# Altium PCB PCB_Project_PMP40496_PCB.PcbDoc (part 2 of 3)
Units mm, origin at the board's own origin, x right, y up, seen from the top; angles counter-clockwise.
Board outline 140 x 100 mm, 4 copper layers (Top Layer, Signal Layer 1, Signal Layer 2, Bottom Layer), stack 1.565 mm thick; 186 components, 128 nets, 605 pads, 270 vias.
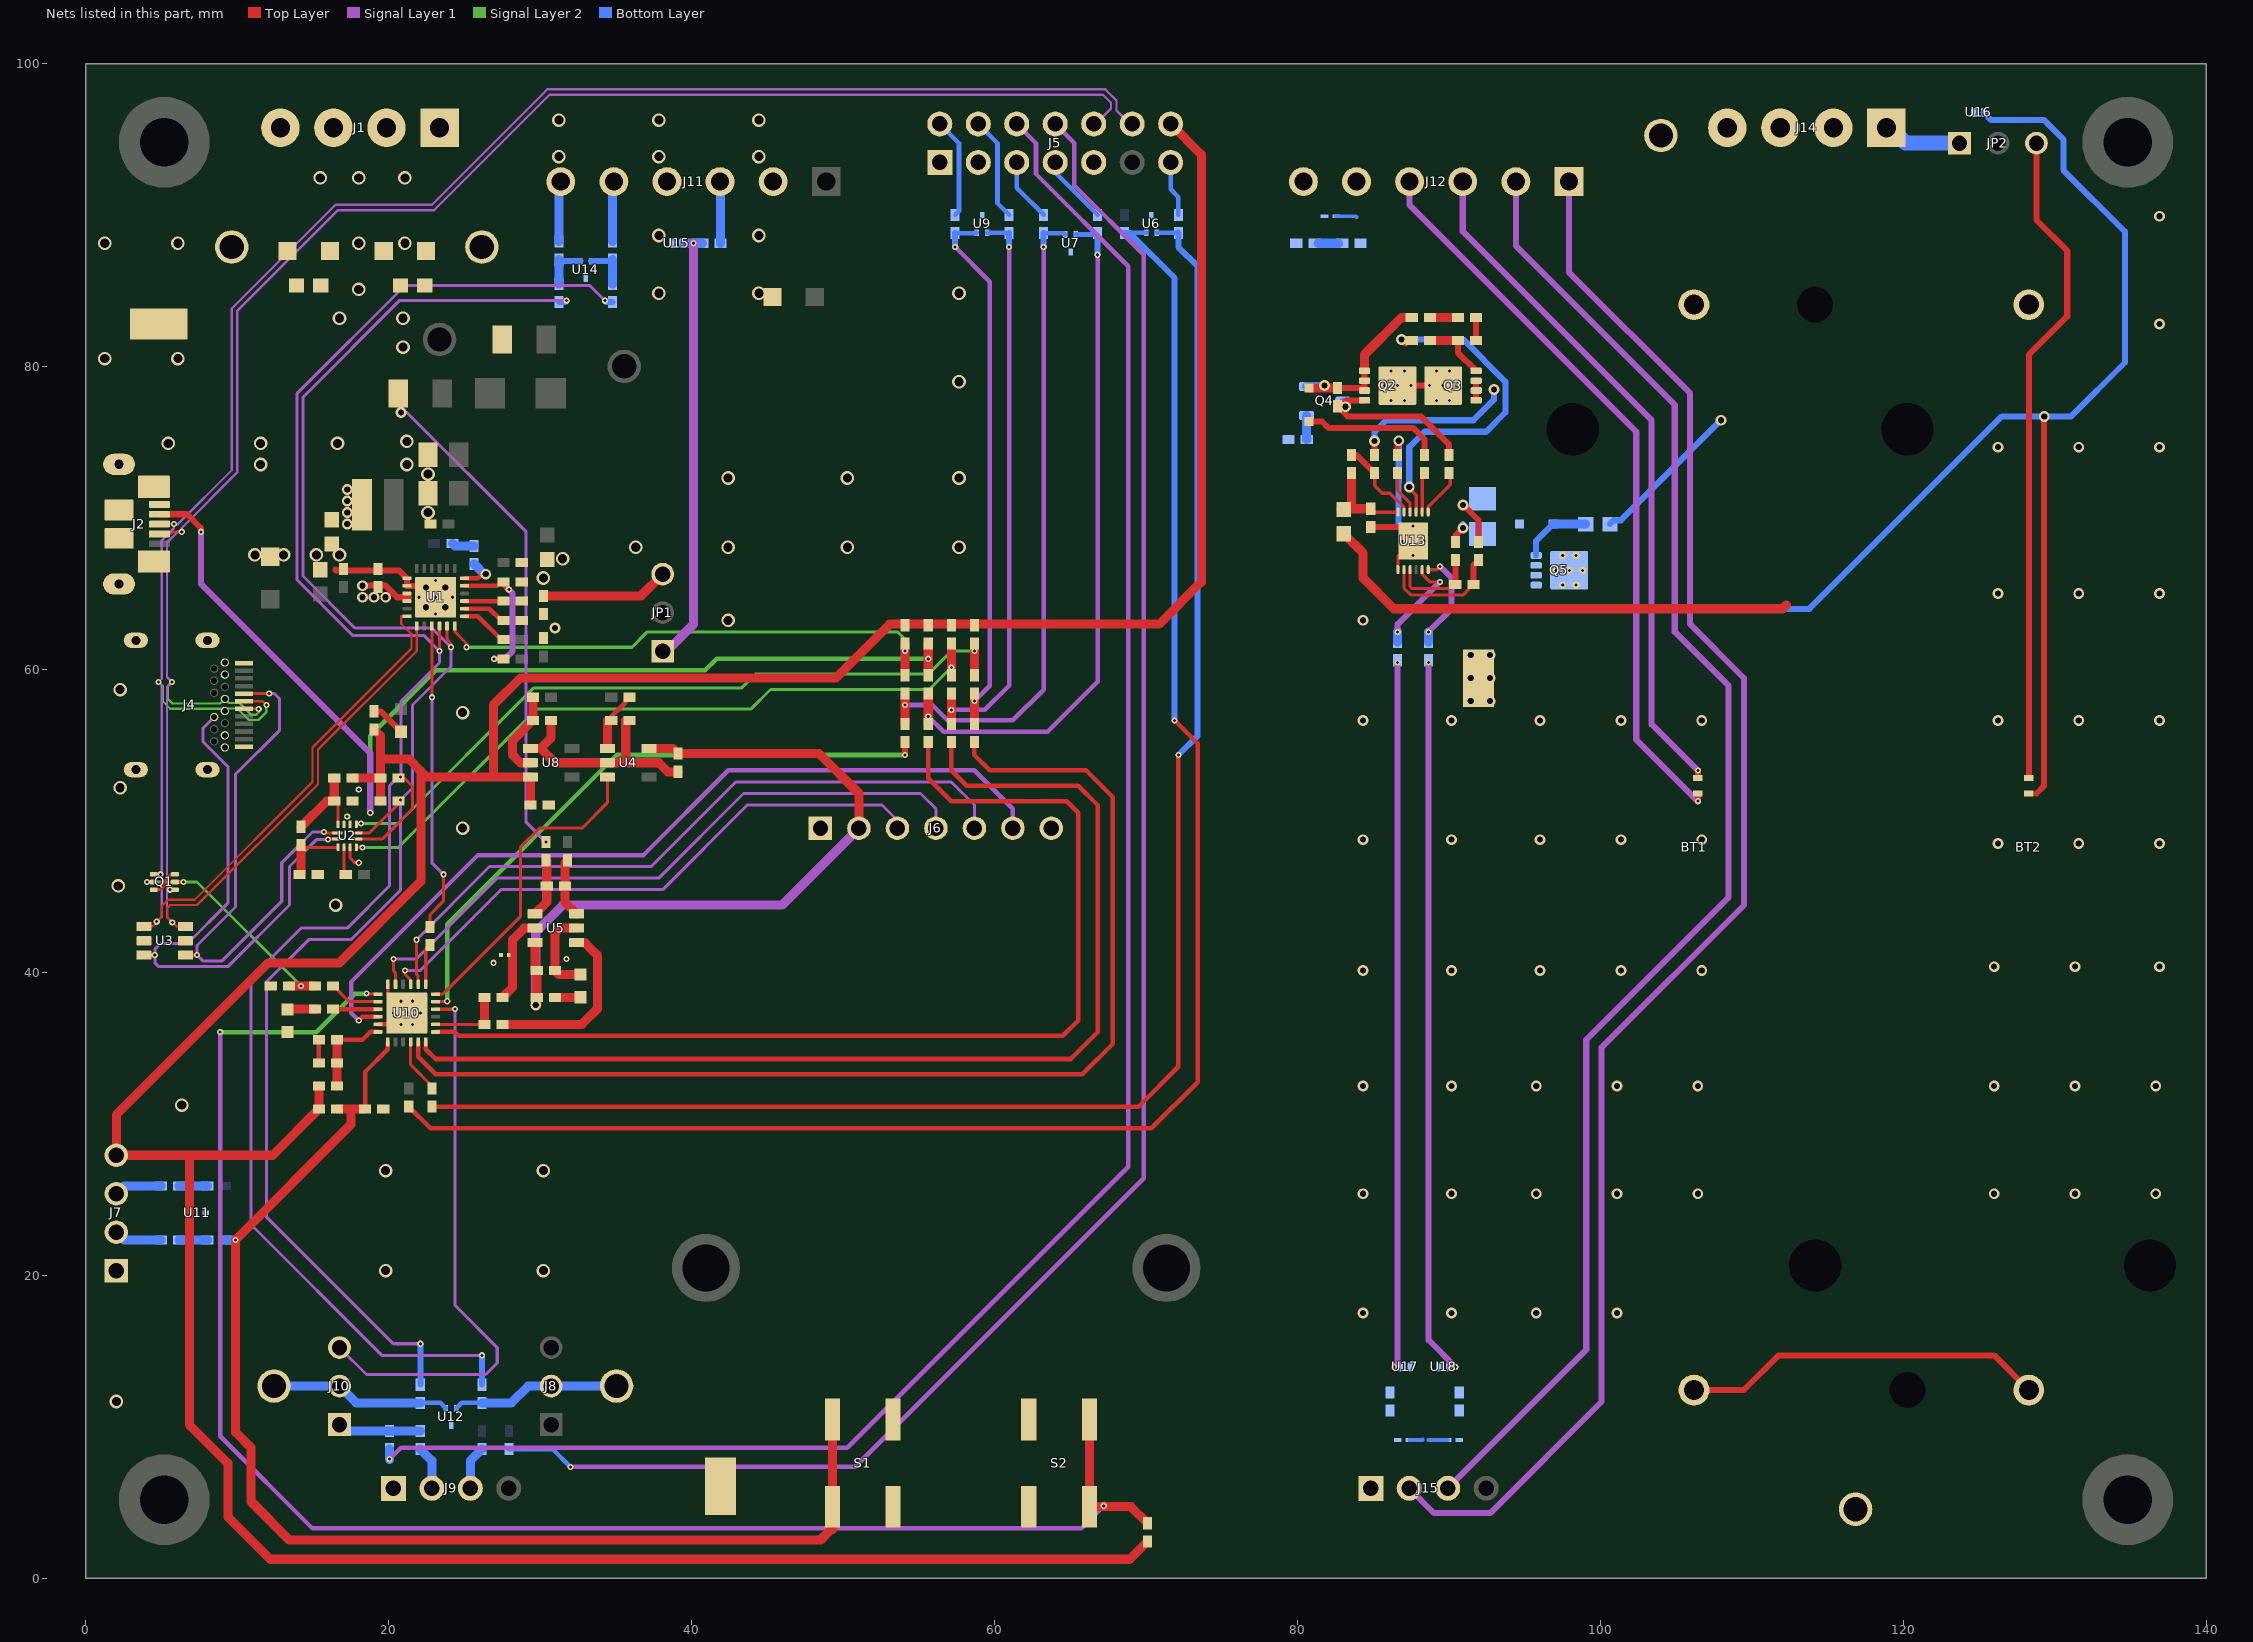
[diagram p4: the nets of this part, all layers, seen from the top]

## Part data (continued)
R5 R11 R12 R38 R41 R44 R49 R51 R53 R54 R68: library part CMP-0026994-4, "RES, 10 k, 5%, 0.1 W, AEC-Q200 Grade 0, 0402", Manufacturer=Panasonic, Power_W=100mW, Supplier Part Number 1=P10KJCT-ND, TempCo="200 ppm/C", Tolerance_%=5%, Value2=0.1W, Value_Code=10k0, ValueDisplayed=10k
R6: library part CMP-0026464-2, "RES, 5.23 k, 1%, 0.063 W, AEC-Q200 Grade 0, 0402", Manufacturer=Vishay-Dale, Power_W=63mW, Supplier Part Number 1=541-5.23KLCT-ND, TempCo="100 ppm/C", Tolerance_%=1%, Value2=0.063W, Value_Code=5k23, ValueDisplayed=5.23k
R7 R13 R14 R16 R17 R18 R19 R20 R21 R22 R23 R27 R28 R29 R30 R32 R33 R34 R35 R37 R39 R40 R42 R43 R61 R62 R64 R65 R66 R69 R70 R72 R73 R74 R75 R76 R77 R78 R79 R80: library part CMP-0026722-1, "RES, 100, 1%, 0.063 W, 0402", Manufacturer="Yageo America", Power_W=63mW, Supplier Part Number 1=311-100LRCT-ND, TempCo="100 ppm/C", Tolerance_%=1%, Value2=0.063W, Value_Code=100R, ValueDisplayed=100
R8: library part CMP-0026730-1, "RES, 30.1 k, 1%, 0.063 W, 0402", Manufacturer="Yageo America", Power_W=63mW, Supplier Part Number 1=311-30.1KLRCT-ND, TempCo="100 ppm/C", Tolerance_%=1%, Value2=0.063W, Value_Code=30k1, ValueDisplayed=30.1k
R9 R15 R26 R31: "RES, 1.00, 1%, 0.063 W, 0402", Manufacturer=Vishay-Dale, Power_W=0.063, Supplier Part Number 1=541-1.00LLCT-ND, TempCo="100 ppm/C", Tolerance_%=1, Value1=1%, Value2=0.063W, Value_Code=1R00, ValueDisplayed=1.00
R10: library part CMP-0026603-2, "RES, 909 k, 1%, 0.063 W, AEC-Q200 Grade 0, 0402", Manufacturer=Vishay-Dale, Power_W=63mW, Supplier Part Number 1=541-909KLCT-ND, TempCo="100 ppm/C", Tolerance_%=1%, Value2=0.063W, Value_Code=909k
R24 R25 R63: library part CMP-0026717-1, "RES, 10.0, 1%, 0.063 W, 0402", Manufacturer=Rohm, Power_W=63mW, Supplier Part Number 1=RHM10.0LCT-ND, TempCo="100 ppm/C", Tolerance_%=1%, Value2=0.063W, Value_Code=10R0, ValueDisplayed=10.0
R36 R45: library part CMP-0026737-1, "RES, 47.0 k, 1%, 0.0625 W, 0402", Manufacturer="Yageo America", Power_W=62.5mW, Supplier Part Number 1=311-47.0KLRCT-ND, TempCo="100 ppm/C", Tolerance_%=1%, Value2=0.0625W, Value_Code=47k0, ValueDisplayed=47.0k
R46 R47 R48: library part CMP-0026668-1, "RES, 1.50 k, 1%, 0.1 W, AEC-Q200 Grade 0, 0402", Manufacturer=Panasonic, Power_W=100mW, Supplier Part Number 1=P1.50KLCT-ND, TempCo="100 ppm/C", Tolerance_%=1%, Value2=0.1W, Value_Code=1k50, ValueDisplayed=1.50k
R50: library part CMP-0026852-3, "RES, 1.0 k, 5%, 0.063 W, AEC-Q200 Grade 0, 0402", Manufacturer=Vishay-Dale, Power_W=63mW, Supplier Part Number 1=541-1.0KJCT-ND, TempCo="200 ppm/C", Tolerance_%=5%, Value2=0.063W, Value_Code=1k00, ValueDisplayed=1.0k
R52: library part CMP-0026823-3, "RES, 100 k, 5%, 0.063 W, AEC-Q200 Grade 0, 0402", Manufacturer=Vishay-Dale, Power_W=63mW, Supplier Part Number 1=541-100KJCT-ND, TempCo="200 ppm/C", Tolerance_%=5%, Value2=0.063W, Value_Code=100k
R55 R56: library part CMP-0026826-2, "RES, 10 M, 5%, 0.063 W, AEC-Q200 Grade 0, 0402", Manufacturer=Vishay-Dale, Power_W=63mW, Supplier Part Number 1=541-10MJCT-ND, TempCo="200 ppm/C", Tolerance_%=5%, Value2=0.063W, Value_Code=10M0, ValueDisplayed=10M
R57: library part CMP-0025899-5, "RES, 1.0 k, 5%, 0.1 W, 0603", Manufacturer=Yageo, Power_W=100mW, Supplier Part Number 1=311-1.0KGRCT-ND, TempCo="100 ppm/C", Tolerance_%=5%, Value2=0.1W, Value_Code=1k00, ValueDisplayed=1.0k
R58: library part CMP-0026434-2, "RES, 4.99, 1%, 0.063 W, AEC-Q200 Grade 0, 0402", Manufacturer=Vishay-Dale, Power_W=63mW, Supplier Part Number 1=541-4.99LLCT-ND, TempCo="100 ppm/C", Tolerance_%=1%, Value2=0.063W, Value_Code=4R99, ValueDisplayed=4.99
R59 R60: library part CMP-0026951-5, "RES, 5.1 k, 5%, 0.063 W, AEC-Q200 Grade 0, 0402", Manufacturer=Vishay-Dale, Power_W=63mW, Supplier Part Number 1=541-5.1KJCT-ND, TempCo="200 ppm/C", Tolerance_%=5%, Value2=0.063W, Value_Code=5k10, ValueDisplayed=5.1k
R67: library part CMP-0021991-4, "RES, 100, 1%, 0.1 W, AEC-Q200 Grade 0, 0603", Manufacturer=Vishay-Dale, Power_W=100mW, Supplier Part Number 1=541-100HCT-ND, TempCo="100 ppm/C", Tolerance_%=1%, Value2=0.1W, Value_Code=100R, ValueDisplayed=100
R71: library part CMP-0018569-2, "RES, 0.001, 1%, 1 W, 1206", Manufacturer=Vishay-Dale, Power_W=1W, Supplier Part Number 1=54X6165, TempCo="275 ppm/C", Tolerance_%=1%, Value_Code=1L000, ValueDisplayed=0.001
RT1 RT2: library part CMP-0002344-2, "Thermistor NTC, 10.0k ohm, 1%, 0402", Manufacturer=MuRata, Power_W=100mW, Supplier Part Number 1=490-4801-1-ND, Tolerance_%=1%
S1 S2: library part CMP-0002310-1, "SWITCH TACTILE SPST-NO 0.05A 12V", CurrentRating_mA=50A, Manufacturer="Omron Electronic Components", Supplier Part Number 1=SW1064CT-ND
SH-JP1 SH-JP2 SH-JP3 SH-JP4: library part CMP-0003614-1, "Shunt, 100mil, Gold plated, Black", Alternate Manufacturer=Samtec, Alternate PartNumber=SNT-100-BK-G, Manufacturer=3M, Supplier Part Number 1=3M9580-ND
TP1 TP2 TP9: "Test Point, Multipurpose, Red, TH", Color=Red, Manufacturer=Keystone, Supplier Part Number 1=36-5010-ND
TP3 TP4 TP10: "Test Point, Multipurpose, Orange, TH", Color=Orange, Manufacturer=Keystone, Supplier Part Number 1=36-5013-ND
TP5 TP6 TP11: library part 5019, "Test Point, Miniature, SMT", Manufacturer=Keystone, Supplier Part Number 1=36-5019TR-ND
TP7: "Test Point, Compact, White, TH", Color=White, Manufacturer=Keystone, Supplier Part Number 1=36-5007-ND
TP8: "Test Point, Compact, Orange, TH", Color=Orange, Manufacturer=Keystone, Supplier Part Number 1=36-5008-ND
U1: library part CMP-0076878-5, "I2C Controlled, 2-Cell, 2A Boost-Mode Battery Charger for USB Input, RGE0024H (VQFN-24)", Alternate Manufacturer="Texas Instruments", Alternate PartNumber=BQ25881RGET
U2: library part CMP-0073635-2, "USB Type-C Configuration Channel Logic and Port Control, RWB0012A (X2QFN-12)", Alternate Manufacturer="Texas Instruments", Operating Temperature Range="-40 to 85 C", Rating=Catalog
U3: library part CMP-0066605-1, "Quad-Channel High-Speed ESD Protection Device, DBV0006A (SOT-23-6)", Alternate Manufacturer="Texas Instruments"
U4: library part CMP-0073793-1, "150-mA, 30-V, Ultra-Low IQ, Wide Input Low-Dropout Regulator with Reverse Current Protection, DBV0005A (SOT-23-5)", Alternate Manufacturer="Texas Instruments", Alternate PartNumber=TPS70933DBVT
U5: library part CMP-0013232-2, "Bidirectional, Low- and High-Side Measurement, Multichannel, Voltage Output, Current-Sense Amplifier, DBV0006A (SOT-6)", Alternate Manufacturer="Texas Instruments"
U6 U7 U9 U11 U12 U14: library part CMP-0043103-2, "ESD / Surge Solution for High Speed, Low Voltage Interface, 2 Channels, -40 to +85 degC, 3-pin SOT (DRT), Green (RoHS & no Sb/Br)", Breakdown Voltage(Min)(V)=4.5, Differential Capacitance(pF)=0.05, IO Capacitance(Typ)(pF)=0.7, IO Leakage Current(nA)=10, Manufacturer="Texas Instruments"
U8: library part CMP-0035588-1, "Single Output LDO, 150 mA, Fixed 3.3 V Output, 2.5 to 24 V Input, with Ultra-Low IQ, 5-pin SOT-23 (DBV), -40 to 125 degC, Green (RoHS & no Sb/Br)", Manufacturer="Texas Instruments"
U10: library part CMP-0076607-2, "MSP430FR2433 16 MHz Ultra-Low-Power Microcontroller with 16 KB FRAM, 4 KB RAM, 19 IO, 4 Timers, RGE0024H (VQFN-24)", Alternate Manufacturer="Texas Instruments", Alternate PartNumber=MSP430FR2433IRGET
U13: library part CMP-0076164-1, "Battery Fuel Gauge with Integrated Protector for 1-2 Series Packs, DRZ0012A (VSON-12)", Alternate Manufacturer="Texas Instruments", Alternate PartNumber=BQ28Z610DRZT
U15 U16 U17 U18: library part CMP-0084110-2, "1-Channel 30 kV ESD Protection Diode With Low Clamping Voltage in 0402 Package, DPY0002A (X1SON-2)", Alternate Manufacturer="Texas Instruments", Operating Temperature Range="-40 to 125 C", Rating=Catalog

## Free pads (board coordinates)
  round 6 hole 3.2: 1(5.2,5.2) 1(5.2,94.8) 1(134.8,5.2) 1(134.8,94.8)
  round 4.5 hole 3.1: 1(40.948,20.502) 1(71.348,20.502)

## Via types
v1: diameter 0.406, hole 0.203, Top Layer to Bottom Layer, 92 vias
v2: diameter 0.711, hole 0.406, Top Layer to Bottom Layer, 89 vias
v3: diameter 0.9, hole 0.6, Top Layer to Bottom Layer, tented top, 59 vias
v4: diameter 0.5, hole 0.2, Top Layer to Bottom Layer, 27 vias
v5: diameter 0.5, hole 0.2, Top Layer to Bottom Layer, tented both sides, 3 vias

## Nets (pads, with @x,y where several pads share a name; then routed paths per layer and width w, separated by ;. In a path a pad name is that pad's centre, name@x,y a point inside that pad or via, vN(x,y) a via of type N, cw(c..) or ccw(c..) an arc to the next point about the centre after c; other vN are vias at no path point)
3.3V: C17.1 J5.14 J7.4 R9.2 R31.2 R36.2 R38.2 R41.2 R44.2 R45.2 R46.2 R49.2 R51.2 R53.2 U8.3 | length 244.8
  Top Layer w0.6: R31.2@15.402,32.512 R36.2@15.402,30.988 12.354,27.94 6.858,27.94 ; R9.2@17.618,52.832 R38.2@19.466,52.832 ; R46.2@19.05,56.042 19.466,55.626 19.466,54.102 ; R41.2@19.466,51.308 R38.2@19.466,52.832 ; C17.1@29.376,51.054 29.376,52.885 U8.3@29.363,52.898 26.924,52.898 ; R45.2@70.104,2.448 68.926,1.27 12.192,1.27 9.398,4.064 9.398,7.62 6.858,10.16 6.858,27.94 ; J5.14@71.628,96.012 73.66,93.98 73.66,65.786 70.866,62.992 53.086,62.992 49.53,59.436 28.702,59.436 26.924,57.658 26.924,52.898 ; 6.858,27.94 J7.4@2.032,27.94 2.032,30.607 12.065,40.64 16.764,40.64 22.14,46.016 22.14,53.298 ; R38.2@19.466,52.832 19.466,54.102 ; 19.466,54.102 21.336,54.102 22.14,53.298 ; 22.14,53.298 22.54,52.898 26.924,52.898
3.3V1: C11.1 C13.1 J6.2 R48.2 U4.5 U5.6 | length 50.6
  Top Layer w0.6: U5.6@29.67,41.976 29.67,40.25 C11.1@29.788,40.132 R48.2@29.788,38.354 29.788,37.916 v2(29.718,37.846) ; U4.5@37.197,54.798 38.77,54.798 C13.1@39.12,54.448 48.422,54.448 51.054,51.816 J6.2@51.054,49.53
  Signal Layer 1 w0.6: v2(29.718,37.846) 29.718,42.672 31.496,44.45 45.974,44.45 J6.2@51.054,49.53
CC1: J4.A5 U2.1 U3.4 | length 36.9
  Top Layer w0.2: J4.A5@10.453,58.408 10.462,58.417 v1(12.126,58.417) ; v1(15.748,49.276) 15.802,49.222 U2.1@16.622,49.222
  Top Layer w0.3: U3.4@6.604,41.148 v1(7.366,41.148)
  Signal Layer 1 w0.2: v1(12.126,58.417) 12.449,58.417 12.818,58.048 12.818,55.998 9.906,53.086 9.906,44.323 7.366,41.783 v1(7.366,41.148) 7.747,40.767 9.017,40.767 12.954,44.704 12.954,47.244 14.986,49.276 v1(15.748,49.276)
CC2: J4.B5 U2.2 U3.3 | length 38.1
  Top Layer w0.2: v1(16.002,48.768) 16.056,48.822 U2.2@16.622,48.822
  Top Layer w0.3: U3.3@3.854,41.148 v1(4.572,41.148)
  Signal Layer 1 w0.2: J4.B5@8.493,56.858 7.747,56.112 7.747,55.245 9.398,53.594 9.398,44.577 6.731,41.91 4.953,41.91 4.572,41.529 v1(4.572,41.148) 4.572,40.64 4.826,40.386 9.398,40.386 13.462,44.45 13.462,46.99 15.24,48.768 v1(16.002,48.768)
CE: R37.2 U1.3 | length 20.7
  Top Layer w0.2: v1(22.86,58.166) 22.864,58.17 U1.3@22.864,62.87 ; R37.2@22.864,43.136 R37.2@22.733,43.005 22.733,43.815 23.622,44.704 v1(23.622,46.482)
  Signal Layer 1 w0.2: v1(22.86,58.166) 22.86,47.244 v1(23.622,46.482)
CLK: J6.3 U10.15 | length 39
  Top Layer w0.2: v1(21.082,40.132) 21.082,39.878 21.459,39.501 U10.15@21.459,39.225
  Signal Layer 1 w0.2: v1(21.082,40.132) 22.098,40.132 27.432,45.466 38.1,45.466 43.688,51.054 52.578,51.054 53.594,50.038 J6.3@53.594,49.53
D_SHORT: R50.2 U10.20 | length 3.4
  Top Layer w0.2: R50.2@16.348,39.116 17.389,38.075 U10.20@19.309,38.075
DATA_N: J2.2 J4.A7 J4.B7 J5.10 Q1.4 U1.1 U3.6 | length 148.2
  Top Layer w0.152: J2.2@4.872,68.946 5.638,68.946 5.78,69.088 v1(6.35,69.088) ; v1@5.581,45.466 v1(5.588,45.466) Q1.4@5.907,45.466 ; U3.6@6.604,43.048 5.988,43.048 v1(5.729,43.307) 5.407,43.629 5.407,44.257 5.6,44.45 7.361,44.45 15.342,52.431 15.342,54.712 21.873,61.243 21.873,62.484 21.864,62.493 U1.1@21.864,62.87 ; J4.A7@10.453,57.408 11.426,57.408 v1(11.43,57.404)
  Signal Layer 1 w0.152: v1(5.729,43.307) 5.385,43.651 5.385,45.466 5.385,58.852 v1(5.715,59.182) 5.385,59.512 5.385,68.377 6.096,69.088 v1(6.35,69.088) 6.35,69.345 10.008,73.002 10.008,83.673 16.657,90.322 23.012,90.322 30.632,97.942 67.158,97.942 67.691,97.409 67.691,97.028 66.675,96.012 J5.10@66.548,96.012
  Signal Layer 2 w0.152: v1(5.715,59.182) 5.448,58.915 5.448,58.052 5.74,57.76 8.895,57.76 J4.B7@9.193,58.058 9.466,57.785 10.16,57.785 10.922,57.023 11.271,57.023 11.43,57.182 v1(11.43,57.404)
DATA_P: J2.3 J4.A6 J4.B6 J5.12 Q1.1 U1.24 U3.1 | length 152
  Top Layer w0.152: U3.1@3.854,43.048 4.43,43.048 4.699,43.317 v1(4.699,43.355) 5.051,43.707 5.051,44.404 5.453,44.806 7.214,44.806 14.986,52.578 14.986,54.859 21.518,61.391 21.518,62.337 20.838,63.017 20.838,63.52 U1.24@21.214,63.52 ; Q1.1@4.507,46.482 v1(4.953,46.482) ; J2.3@4.872,69.596 v1(5.842,69.596) ; J4.A6@10.453,57.908 11.688,57.908 v1(11.938,57.658)
  Signal Layer 1 w0.152: v1(4.699,43.355) 5.029,43.685 5.029,46.482 5.029,58.979 v1(4.826,59.182) 5.029,59.385 5.029,68.524 5.842,69.337 v1(5.842,69.596) 6.099,69.596 9.652,73.149 9.652,83.82 16.51,90.678 22.865,90.678 30.381,98.194 30.485,98.298 67.305,98.298 67.409,98.194 68.047,97.556 68.047,96.901 68.936,96.012 J5.12@69.088,96.012
  Signal Layer 2 w0.152: v1(4.826,59.182) 5.093,58.915 5.093,57.904 5.593,57.404 9.047,57.404 J4.B6@9.193,57.258 9.364,57.429 10.013,57.429 10.775,56.667 11.419,56.667 11.938,57.187 v1(11.938,57.658)
DC: J6.6 U10.22 | length 55.9
  Top Layer w0.3: v1(18.034,36.83) 18.279,37.075 U10.22@19.309,37.075
  Signal Layer 1 w0.3: v1(18.034,36.83) 17.526,37.338 17.526,39.37 25.908,47.752 36.83,47.752 42.418,53.34 58.674,53.34 61.214,50.8 J6.6@61.214,49.53
EN_LDO: U4.3 U10.12 | length 20.9
  Top Layer w0.2: U10.12@23.109,38.575 23.589,38.575 23.876,38.862 28.702,43.688 28.702,48.26 29.972,49.53 32.766,49.53 34.447,51.211 U4.3@34.447,52.898
GND: C1.2 C2.2 C3.2 C4.2 C5.2 C7.2 C8.2 C9.2 C10.2 C11.2 C12.2 C13.2 C16.2 C17.2 C18.2 C19.2 C20.2 C29.2 C30.2 C31.2 C32.2 D1.2 D3.2 D4.2 D5.2 D7.2 D8.2 J1.2 J1.3 J2.5 J2.6 J2.7 J2.8 J2.9 J2.10 J2.11 J4.A1 J4.A12 J4.B1 J4.B12 J4.M1 J4.M2 J4.S1 J4.S2 J4.S3 J4.S4 J5.1 J5.3 J5.9 J6.1 J6.7 J7.1 J9.1 J11.2 J11.4 NT1.1 R2.1 R5.1 R8.1 R12.2 R52.1 R54.1 S1.1 S1.2 S2.1 S2.2 TP5.1 TP6.1 U1.19 U1.20 U1.25@23.114,64.77 U2.5 U2.10 U2.11 U3.2 U3.5 U4.2 U5.2 U6.3 U7.3 U8.1 U9.3 U10.18 U10.23 U10.25@21.209,37.325 U11.3 U12.3 U14.3 U15.2 | length 35.6
  Top Layer w0.2: U2.5@17.472,48.272 17.472,47.552 17.78,47.244 v1(18.034,47.244) ; U10.18@19.959,39.225 19.959,38.575 v1(21.209,37.325)
  Top Layer w0.3: C18.2@15.402,34.036 C19.2@15.402,35.56 ; U10.23@19.309,36.575 20.459,36.575 U10.25@21.152,37.268
  Top Layer w0.4: 16.51,66.586 16.548,66.548 20.686,66.548 U1.19@21.214,66.02 U1.20@21.214,65.52 22.364,65.52 v4(23.114,64.77)
  Top Layer w0.6: C16.2@30.738,56.642 30.738,55.498 30.038,54.798 30.988,53.848 U4.2@34.447,53.848 35.56,53.848 ; U5.2@32.42,42.926 31.334,42.926 30.988,42.58 C11.2@30.988,40.132 31.254,39.866 D8.2@32.674,39.866 ; C12.2@35.66,56.642 35.66,53.948 35.56,53.848 ; C13.2@39.12,53.248 38.446,53.248 37.846,53.848 35.56,53.848
  other v1: 20.828,36.576 21.59,36.576 20.32,37.338 22.098,37.338 20.828,38.1 21.59,38.1 26.924,40.64 31.75,40.894 17.272,50.292 18.034,52.07
  other v2: 30.988,62.738 22.479,64.11 23.749,64.11 22.479,65.405 23.749,65.405
  other v3: 2.032,11.684 19.812,20.32 30.226,20.32 19.812,26.924 30.226,26.924 6.35,31.242 16.51,44.45 2.159,45.72 24.892,49.53 2.286,52.197 24.892,57.15 2.286,58.674 42.418,63.246 30.226,66.04 31.496,67.31 11.176,67.564 13.081,67.564 15.24,67.564 16.764,67.564 36.322,68.072 42.418,68.072 50.292,68.072 57.658,68.072 22.606,70.358 42.418,72.644 50.292,72.644 57.658,72.644 22.606,72.898 11.557,73.533 21.209,73.533 5.461,74.93 11.557,74.93 16.637,74.93 21.209,75.057 57.658,78.994 1.27,80.518 6.096,80.518 20.955,81.28 16.764,83.185 20.955,83.185 37.846,84.836 44.45,84.836 57.658,84.836 18.034,85.09 1.27,88.138 6.096,88.138 18.034,88.138 21.082,88.138 37.846,88.646 44.45,88.646 15.494,92.456 18.034,92.456 21.082,92.456 31.242,93.853 37.846,93.853 44.45,93.853 31.242,96.266 37.846,96.266 44.45,96.266
  other v4: 23.114,63.67 22.014,64.77 24.214,64.77 23.114,65.87
GND1: C25.2 E1.1 E2.1 E3.1 J12.5 J15.1 R68.1 R69.1 R71.1 U17.2 U18.2 | length 6.4
  Top Layer w0.4: v2(90.932,70.866) 91.948,69.85 R69.1@91.948,68.418
  Bottom Layer w0.254: E1.1@82.55,89.916 83.845,89.916 83.896,89.865 ; E3.1@87.376,9.144 88.24,9.144 88.265,9.169 ; 88.646,9.144 E2.1@89.916,9.144
  other v2: 84.328,17.526 90.17,17.526 95.758,17.526 101.092,17.526 84.328,25.4 90.17,25.4 95.758,25.4 101.092,25.4 106.426,25.4 125.984,25.4 131.318,25.4 136.652,25.4 84.328,32.512 90.17,32.512 95.758,32.512 101.092,32.512 106.426,32.512 125.984,32.512 131.318,32.512 136.652,32.512 84.328,40.132 90.17,40.132 96.012,40.132 101.346,40.132 106.68,40.132 125.984,40.386 131.318,40.386 136.906,40.386 126.238,48.514 131.572,48.514 136.906,48.514 84.328,48.768 90.17,48.768 96.012,48.768 101.346,48.768 106.68,48.768 84.328,56.642 90.17,56.642 96.012,56.642 101.346,56.642 106.68,56.642 126.238,56.642 131.572,56.642 136.906,56.642 84.328,63.246 126.238,65.024 131.572,65.024 136.906,65.024 126.238,74.676 131.572,74.676 136.906,74.676 136.906,82.804 136.906,89.916
GND2: C27.2 C28.2 D10.2 Q5.1 Q5.2 Q5.3 R70.1 R71.2 RT2.1 TP11.1 U13.1 U13.13 U16.2 | length 107.1
  Top Layer w0.22: U13.1@86.63,66.588 86.63,67.488 U13.13@87.63,68.488
  Top Layer w0.4: C27.2@84.836,69.412 87.579,69.412 v4(87.63,69.463) ; C28.2@86.614,74.168 86.614,75.024 v2(86.685,75.095) ; R70.1@90.424,68.418 90.424,68.834 v2(90.932,69.342) ; 128.778,51.816 129.286,52.324 v2(129.286,76.708)
  Bottom Layer w0.4: v2(86.685,75.095) 86.685,72.351 86.67,72.336 86.67,69.61 86.868,69.412 ; v2(90.932,69.342) v2@90.932,69.596 ; 94.996,64.008 113.792,64.008 126.492,76.708 v2(129.286,76.708) 131.064,76.708 134.62,80.264 134.62,88.9 130.556,92.964 130.556,94.996 129.286,96.266 125.801,96.266 U16.2@125.293,96.774
  other v2: 91.44,57.912 92.71,57.912 91.44,59.436 92.71,59.436 91.44,60.96 92.71,60.96
  other v4: 87.63,67.513 86.905,68.488 88.355,68.488
I_SYS: C14.1 R16.1 U10.8 | length 5
  Top Layer w0.2: U10.8@23.109,36.575 R16.1@26.324,36.576
  Top Layer w0.6: R16.1@26.324,36.576 C14.1@26.324,38.354
ID_B: J2.4 R21.2 R44.1 | length 72.7
  Top Layer w0.4: J2.4@4.872,70.246 6.716,70.246 7.62,69.342 v1(7.62,69.088)
  Top Layer w0.6: R21.2@55.626,59.62 v1(55.626,60.706) R44.1@55.626,61.722
  Signal Layer 1 w0.4: v1(7.62,69.088) 7.62,65.659 18.796,54.483 v1(18.796,50.546)
  Signal Layer 2 w0.3: v1(18.796,50.546) 18.796,55.626 23.114,59.944 40.894,59.944 41.656,60.706 v1(55.626,60.706)
ID_B_MCU: R23.2 U10.7 | length 69.9
  Top Layer w0.3: U10.7@23.109,36.075 24.377,36.075 24.638,35.814 64.516,35.814 65.532,36.83 65.532,50.546 64.77,51.308 57.15,51.308 55.626,52.832 R23.2@55.626,55.21
ID_C: R27.2 R49.1 U2.9 | length 47.6
  Top Layer w0.2: U2.9@17.872,49.772 17.936,49.836 v1(18.188,49.836)
  Top Layer w0.6: R27.2@58.674,59.62 v1(58.674,61.214) R49.1@58.674,61.722
  Signal Layer 2 w0.2: v1(18.188,49.836) 20.626,49.836 29.562,58.772 43.278,58.772 44.196,59.69 55.626,59.69 57.15,61.214 v1(58.674,61.214)
ID_C_MCU: R76.2 U10.5 | length 75.6
  Top Layer w0.3: U10.5@21.959,35.425 21.959,34.429 23.114,33.274 65.786,33.274 67.818,35.306 67.818,51.562 66.04,53.34 59.69,53.34 58.674,54.356 R76.2@58.674,55.21
INT: R53.1 R79.2 U1.6 | length 34.2
  Top Layer w0.2: U1.6@24.364,62.87 24.384,62.85 24.384,62.484 25.146,61.722 v1(25.146,61.468)
  Top Layer w0.6: R79.2@54.102,59.62 54.102,61.144 R53.1@54.102,61.722
  Signal Layer 2 w0.2: v1(25.146,61.468) 36.068,61.468 37.084,62.484 53.594,62.484 54.102,61.976 v1@54.102,61.144
  other v1: 54.102,61.214
INT_C: R29.2 R51.1 U2.6 | length 46.3
  Top Layer w0.2: U2.6@17.872,48.272 18.276,48.272 v1(18.288,48.26)
  Top Layer w0.6: R29.2@57.15,59.62 v1(57.15,60.128) R51.1@57.15,61.722
  Signal Layer 2 w0.2: v1(18.288,48.26) 20.666,48.26 29.81,57.404 43.942,57.404 45.212,58.674 55.696,58.674 v1(57.15,60.128)
INT_C_MCU: R77.2 U10.6 | length 73.3
  Top Layer w0.3: U10.6@22.459,35.425 22.459,34.945 23.114,34.29 65.024,34.29 66.802,36.068 66.802,51.054 65.532,52.324 58.166,52.324 57.15,53.34 R77.2@57.15,55.21
INT_MCU: R80.2 U10.11 | length 41.6
  Top Layer w0.2: U10.11@23.109,38.075 23.851,38.075 v1(23.876,38.1)
  Top Layer w0.4: v1(54.102,54.356) R80.2@54.102,55.21
  Signal Layer 2 w0.3: v1(23.876,38.1) 23.876,43.18 35.052,54.356 v1(54.102,54.356)
KEY: R45.1 S2.3 S2.4 U10.19 | length 109.7
  Top Layer w0.2: v1(18.542,38.608) 18.575,38.575 U10.19@19.309,38.575
  Top Layer w0.6: S2.4@66.262,10.495 S2.3@66.262,4.745 69.007,4.745 R45.1@70.104,3.648
  Signal Layer 1 w0.3: v1(8.89,36.068) 8.89,9.398 14.986,3.302 65.716,3.302 v1(67.21,4.797)
  Signal Layer 2 w0.3: v1(8.89,36.068) 15.24,36.068 17.78,38.608 v1(18.542,38.608)
LED0: R47.2 U10.21 | length 2.8
  Top Layer w0.3: R47.2@16.475,37.579 16.479,37.575 U10.21@19.309,37.575
LOAD1: C3.1 D1.1 J1.4 R1.2 R25.1 TP2.1 | length 32.5
  Signal Layer 1 w0.2: v2(20.828,76.962) 21.209,76.962 29.083,69.088 29.083,49.911 v1(30.388,48.606)
LOAD2: C9.1 D4.1 J1.1 R4.1 TP4.1
MOSI: J6.4 U10.17 | length 43.8
  Top Layer w0.2: v1(20.32,40.894) 20.32,40.132 20.459,39.993 U10.17@20.459,39.225
  Signal Layer 1 w0.2: v1(20.32,40.894) 21.822,40.894 27.156,46.228 37.846,46.228 43.434,51.816 55.118,51.816 56.134,50.8 J6.4@56.134,49.53
NetBT1_1: BT1.1 C22.1 J14.4 Q3.1 Q3.2 Q3.3 R56.2 R57.2 R58.2 TP9.1 | length 23.9
  Top Layer w0.4: R58.2@85.09,74.168 v2(85.09,75.092) ; R56.2@91.789,81.717 C22.1@91.789,83.241 ; Q3.1@91.793,77.765 Q3.2@91.793,78.415 Q3.3@91.793,79.065
  Bottom Layer w0.4: v2(85.09,75.092) 85.09,75.692 85.852,76.454 91.612,76.454 92.964,77.806 v2(92.964,78.486) ; R57.2@100.622,69.596 100.876,69.85 101.346,69.85 v2(107.95,76.454)
NetBT1_2: BT1.2 BT2.1 J14.3 R67.2 TP10.1 | length 56.3
  Top Layer w0.4: BT1.2@106.172,12.44 109.468,12.44 111.76,14.732 125.978,14.732 BT2.1@128.27,12.44
  Top Layer w0.6: R67.2@83.058,68.958 84.328,67.688 84.328,66.04 86.36,64.008 112.014,64.008 112.268,64.262
NetBT2_2: BT2.2 J14.2 Q5.5 Q5.6 Q5.7 Q5.8 Q5.9@97.932,66.548
  other v4: 97.508,65.573 98.384,65.573 97.07,66.548 97.946,66.548 97.508,67.523 98.384,67.523
  other v5: 98.822,66.548
NetC6_1: C6.1 R3.1 | length 1.5
  Bottom Layer w0.6: C6.1@24.222,68.326 24.384,68.164 R3.1@25.654,68.164
NetC10_1: C10.1 R9.1 R11.1 U2.12 | length 6.1
  Top Layer w0.2: C10.1@16.418,51.308 16.672,51.054 U2.12@16.672,49.772
  Top Layer w0.6: R11.1@14.224,49.622 15.91,51.308 C10.1@16.418,51.308 R9.1@16.418,52.832
NetC12_1: C12.1 R15.2 U4.1 | length 3.9
  Top Layer w0.3: C12.1@34.452,56.642 35.656,57.846 R15.2@35.656,58.166
  Top Layer w0.4: C12.1@34.46,56.642 C12.1@34.465,56.642
  Top Layer w0.6: U4.1@34.447,54.798 34.447,56.629 C12.1@34.46,56.642
NetC14_2: C14.2 NT1.2 U5.5 | length 5.9
  Top Layer w0.6: C14.2@27.524,38.354 28.194,39.024 28.194,42.164 28.956,42.926 U5.5@29.67,42.926
NetC15_1: C15.1 R24.2 U5.3 | length 3.9
  Top Layer w0.6: R24.2@31.807,47.406 31.645,47.244 C15.1@31.645,45.72 31.645,44.651 U5.3@32.42,43.876
NetC15_2: C15.2 R25.2 U5.4 | length 3.9
  Top Layer w0.6: U5.4@29.67,43.876 30.445,44.651 C15.2@30.445,45.72 30.445,47.349 R25.2@30.388,47.406
NetC16_1: C16.1 R26.2 U8.2 | length 7.3
  Top Layer w0.6: U8.2@29.363,53.848 28.702,53.848 28.194,54.356 28.194,55.306 29.534,56.646 R26.2@29.534,58.166 29.538,58.162 C16.1@29.538,56.642
NetC18_1: C18.1 C19.1 R31.1 U10.24 | length 5.8
  Top Layer w0.3: C19.1@16.764,35.547 18.275,35.547 18.803,36.075 U10.24@19.309,36.075
  Top Layer w0.6: R31.1@16.602,32.512 C18.1@16.602,34.036 C19.1@16.602,35.56
NetC21_1: C21.1 C22.2 | length 1.8
  Top Layer w0.6: C21.1@88.741,83.241 C22.2@90.589,83.241
NetC23_2: C23.2 C25.1 | length 1.3
  Bottom Layer w0.6: C23.2@81.372,88.138 C25.1@82.712,88.138
NetC24_1: C24.1 R58.1 U13.11 | length 5.7
  Top Layer w0.22: R58.1@85.09,72.968 85.09,72.136 85.598,71.628 86.099,71.628 87.03,70.697 U13.11@87.03,70.388
  Top Layer w0.4: C24.1@83.566,74.168 83.89,74.168 R58.1@85.09,72.968
NetC24_2: C24.2 C27.1 R67.1 U13.12 | length 6.2
  Top Layer w0.22: R67.1@83.497,70.612 83.566,70.681 ; C27.1@84.582,70.612 84.806,70.388 U13.12@86.63,70.388
  Top Layer w0.6: R67.1@82.858,70.612 83.497,70.612 C27.1@84.582,70.612 ; 83.566,70.681 C24.2@83.566,72.968
NetC26_1: C26.1 R69.2 U13.2 | length 8
  Top Layer w0.2: U13.2@87.03,66.588 87.03,65.37 87.468,64.932 90.932,64.932 C26.1@91.613,65.613
  Top Layer w0.4: C26.1@91.613,65.613 91.613,66.883 R69.2@91.948,67.218
NetC26_2: C26.2 R70.2 U13.3 | length 5.9
  Top Layer w0.2: U13.3@87.43,66.588 87.43,65.478 87.575,65.333 90.133,65.333 C26.2@90.413,65.613
  Top Layer w0.4: C26.2@90.413,65.613 90.424,65.624 R70.2@90.424,67.218
NetC28_1: C28.1 U13.10 | length 2.9
  Top Layer w0.22: C28.1@86.614,72.968 86.614,71.79 87.43,70.974 U13.10@87.43,70.388
NetD6_1: D6.1 R46.1 | length 2.3
  Top Layer w0.4: R46.1@19.05,57.242 19.478,57.242 D6.1@20.828,55.892
NetD7_1: D7.1 R47.1 | length 1.9
  Top Layer w0.6: D7.1@13.335,37.567 13.347,37.579 R47.1@15.275,37.579
NetD8_1: D8.1 R48.1 | length 1.7
  Top Layer w0.6: R48.1@30.988,38.354 32.662,38.354 D8.1@32.674,38.366
NetD9_1: D9.1 R63.2 | length 9.1
  Top Layer w0.4: D9.1@80.772,76.37 81.618,76.37 82.042,75.946 87.63,75.946 88.392,75.184 R63.2@88.392,74.168
NetD10_1: D10.1 Q5.4 R57.1 | length 4.7
  Bottom Layer w0.4: Q5.4@95.757,67.523 95.757,68.495 D10.1@96.858,69.596
  Bottom Layer w0.6: D10.1@96.858,69.596 R57.1@99.022,69.596
NetJ5_2: J5.2 R28.1 | length 6.6
  Bottom Layer w0.3: J5.2@56.388,96.012 57.658,94.742 57.658,90.262 R28.1@57.404,90.008
NetJ5_4: J5.4 R30.1 | length 6.8
  Bottom Layer w0.3: J5.4@58.928,96.012 60.198,94.742 60.198,90.77 R30.1@60.96,90.008
NetJ5_5: J5.5 R78.1 | length 4.2
  Bottom Layer w0.3: J5.5@61.468,93.472 61.468,91.786 R78.1@63.246,90.008
NetJ5_6: J5.6 R14.1 | length 129.3
  Signal Layer 1 w0.3: v1(20.066,7.874) 20.828,8.636 50.292,8.636 68.834,27.178 68.834,86.614 62.738,92.71 62.738,94.742 J5.6@61.468,96.012
  Bottom Layer w0.6: v1(20.066,7.874) R14.1@20.066,8.544
NetJ5_7: J5.7 R22.1 | length 4.7
  Bottom Layer w0.3: J5.7@64.1,93.472 J5.7@64.008,93.472 64.008,92.802 R22.1@66.802,90.008
NetJ5_8: J5.8 R13.2 | length 122.3
  Signal Layer 1 w0.3: v1(32.004,7.366) 50.8,7.366 69.85,26.416 69.85,87.376 65.278,91.948 65.278,94.742 J5.8@64.008,96.012
  Bottom Layer w0.3: R13.2@27.94,8.544 30.826,8.544 v1(32.004,7.366)
NetJ7_2: J7.2 R35.1 | length 3.2
  Bottom Layer w0.6: J7.2@2.032,22.86 2.54,22.352 R35.1@4.988,22.352
NetJ7_3: J7.3 R33.1 | length 3.2
  Bottom Layer w0.6: J7.3@2.032,25.4 2.54,25.908 R33.1@4.988,25.908
NetJ8_2: J8.2 R39.1 TP7.1 U12.2 | length 11.2
  Bottom Layer w0.3: U12.2@24.48,11.243 24.829,11.592 R39.1@26.162,11.592
  Bottom Layer w0.6: R39.1@26.162,11.592 28.102,11.592 29.21,12.7 J8.2@30.734,12.7 TP7.1@35.052,12.7
NetJ9_2: J9.2 R43.1 | length 3.3
  Bottom Layer w0.6: R43.1@22.098,8.544 22.86,7.782 J9.2@22.86,5.954 J9.2@22.606,6.208
NetJ9_3: J9.3 R40.1 | length 3.3
  Bottom Layer w0.6: J9.3@25.654,6.208 J9.3@25.4,5.954 25.4,7.782 R40.1@26.162,8.544
NetJ10_2: J10.2 R42.1 TP8.1 U12.1 | length 11.9
  Bottom Layer w0.3: R42.1@22.098,11.592 23.431,11.592 U12.1@23.78,11.243
  Bottom Layer w0.6: TP8.1@12.446,12.7 J10.2@16.764,12.7 17.872,11.592 R42.1@22.098,11.592
NetJ11_3: J11.3 R61.1 | length 4.1
  Bottom Layer w0.6: R61.1@41.91,88.138 J11.3@41.91,92.065 ; J11.3@42.256,92.065 J11.3@42.393,92.202
NetJ11_5: J11.5 R64.1 | length 4
  Bottom Layer w0.6: R64.1@34.798,88.247 J11.5@34.798,92.143 ; J11.5@35.306,92.126 J11.5@35.382,92.202
NetJ11_6: J11.6 R66.1 | length 4
  Bottom Layer w0.6: R66.1@31.242,88.247 J11.6@31.242,92.093 ; J11.6@31.75,92.075 J11.6@31.877,92.202
NetJ12_3: J12.3 RT1.1 | length 45.8
  Top Layer w0.4: RT1.1@106.426,52.832 v1(106.426,53.34)
  Signal Layer 1 w0.4: J12.3@90.907,92.202 90.907,88.925 103.378,76.454 103.378,56.388 v1(106.426,53.34)
NetJ12_4: J12.4 RT1.2 | length 49.3
  Top Layer w0.4: v1(106.426,51.308) RT1.2@106.426,51.816
  Signal Layer 1 w0.4: J12.4@87.401,92.202 87.401,90.653 102.362,75.692 102.362,55.372 v1(106.426,51.308)
NetJ14_1: J14.1 JP2.1 U16.1 | length 5.4
  Bottom Layer w1: J14.1@118.872,96.012 120.142,94.742 JP2.1@123.698,94.742
NetJP1_1: JP1.1 R61.2 U15.1 | length 29.1
  Signal Layer 1 w0.6: JP1.1@38.1,61.214 38.354,61.214 40.132,62.992 v1(40.121,88.138)
  Bottom Layer w0.6: 39.532,88.138 v1(40.121,88.138) R61.2@40.71,88.138
NetJP1_3: JP1.3 R54.2 | length 8.5
  Top Layer w0.6: R54.2@30.226,64.862 36.668,64.862 JP1.3@38.1,66.294
NetJP2_3: JP2.3 RT2.2 | length 43.8
  Top Layer w0.4: RT2.2@128.27,52.832 128.27,80.772 130.81,83.312 130.81,87.63 128.778,89.662 JP2.3@128.778,94.742
NetQ1_2: Q1.2 Q1.5 R50.1 R52.2 | length 15.7
  Top Layer w0.2: v1(4.064,45.974) Q1.2@4.507,45.974 ; Q1.5@5.907,45.974 v1(6.477,45.974)
  Top Layer w0.6: R52.2@13.427,39.116 v1(14.224,39.116) R50.1@15.148,39.116
  Signal Layer 2 w0.2: v1(4.064,45.974) v1(6.477,45.974) 7.366,45.974 v1(14.224,39.116)
NetQ1_3: Q1.3 Q1.6 | length 2
  Top Layer w0.2: Q1.3@4.507,45.466 4.947,45.466 5.204,45.723 5.204,46.029 5.657,46.482 Q1.6@5.907,46.482
NetQ2_4: Q2.4 Q4.3 R55.1 R59.2 | length 10.4
  Top Layer w0.4: R55.1@82.926,77.1 83.318,76.708 88.138,76.708 89.987,74.859 R59.2@89.987,74.171 ; 83.169,77.765 Q2.4@84.425,77.765
  Bottom Layer w0.4: Q4.3@82.988,77.724 83.169,77.543 v2(83.169,77.343)
NetQ2_5: Q2.5 Q2.6 Q2.7 Q2.8 Q2.9@86.6,78.74 Q3.5 Q3.6 Q3.7 Q3.8 Q3.9@89.618,78.74 | length 3
  Top Layer w0.4: v4(86.614,78.74) v5(87.49,78.74) v5(88.728,78.74) v4(89.604,78.74)
  other v4: 86.176,77.765 87.052,77.765 89.166,77.765 90.042,77.765 85.738,78.74 90.48,78.74 86.176,79.715 87.052,79.715 89.166,79.715 90.042,79.715
NetQ3_4: Q3.4 R56.1 R60.2 | length 4.3
  Top Layer w0.4: R56.1@90.589,81.717 90.589,80.919 Q3.4@91.793,79.715
  Top Layer w0.6: R60.2@88.741,81.717 R56.1@90.589,81.717
NetQ4_1: Q4.1 R68.2 | length 1.6
  Bottom Layer w0.6: Q4.1@80.588,76.774 80.588,75.206 R68.2@80.61,75.184
NetR2_2: R2.2 U1.8 | length 2.9
  Top Layer w0.3: U1.8@25.014,64.02 26.658,64.02 27.432,63.246 R2.2@27.594,63.246
NetR3_2: R3.2 U1.12 | length 2.6
  Top Layer w0.3: U1.12@25.014,66.02 25.888,66.02 26.162,66.294 v2(26.416,66.294)
  Bottom Layer w0.6: R3.2@25.654,66.964 26.324,66.294 v2(26.416,66.294)
NetR5_2: R5.2 U1.9 | length 2.6
  Top Layer w0.3: U1.9@25.014,64.52 27.59,64.52 R5.2@27.594,64.516
NetR7_2: R7.2 U1.7 | length 3.2
  Top Layer w0.3: U1.7@25.014,63.52 25.888,63.52 27.432,61.976 R7.2@27.594,61.976
NetR10_2: R10.2 U2.4 | length 1.8
  Top Layer w0.2: U2.4@17.072,48.272 17.072,46.59 R10.2@17.18,46.482
NetR11_2: R11.2 R12.1 U2.3 | length 4.5
  Top Layer w0.2: R11.2@14.224,48.422 14.386,48.26 16.66,48.26 U2.3@16.672,48.272
  Top Layer w0.6: R12.1@14.132,46.482 14.224,46.574 R11.2@14.224,48.422
NetR16_2: R16.2 U5.1 | length 11.9
  Top Layer w0.6: R16.2@27.524,36.576 32.766,36.576 33.782,37.592 33.782,41.148 32.954,41.976 U5.1@32.42,41.976
NetR17_1: R17.1 R18.2 U6.1 | length 107.9
  Top Layer w0.3: R17.1@22.86,31.15 69.504,31.15 72.136,33.782 v1(72.136,54.356)
  Bottom Layer w0.3: U6.1@70.708,88.833 R18.2@72.111,88.833
  Bottom Layer w0.4: R18.2@72.111,88.833 R18.2@72.136,88.808 72.136,87.884 73.406,86.614 73.406,55.626 v1(72.136,54.356)
NetR19_1: R19.1 R20.2 U6.2 | length 113.6
  Top Layer w0.3: R19.1@21.336,31.15 22.768,29.718 70.358,29.718 73.406,32.766 73.406,55.118 v1(71.882,56.642)
  Bottom Layer w0.3: R20.2@68.58,88.808 68.605,88.833 U6.2@70.008,88.833
  Bottom Layer w0.4: R20.2@68.58,88.808 68.926,88.808 71.882,85.852 v1(71.882,56.642)
NetR21_1: R21.1 R22.2 R23.1 U7.2 | length 45.9
  Top Layer w0.6: R23.1@55.626,56.41 v1(55.626,56.896) R21.1@55.626,58.42
  Signal Layer 1 w0.3: v1(55.626,56.896) 56.642,55.88 63.5,55.88 66.802,59.182 v1(66.802,87.376)
  Bottom Layer w0.3: U7.2@65.374,88.713 R22.2@66.707,88.713
  Bottom Layer w0.4: R22.2@66.707,88.713 66.802,88.618 v1(66.802,87.376)
NetR27_1: R27.1 R28.2 R76.1 U9.2 | length 35.7
  Top Layer w0.6: R76.1@58.674,56.41 v1(58.674,57.912) R27.1@58.674,58.42
  Signal Layer 1 w0.3: v1(57.404,87.884) 59.69,85.598 59.69,58.928 v1(58.674,57.912)
  Bottom Layer w0.3: R28.2@57.404,88.808 58.807,88.808 U9.2@58.832,88.833
  Bottom Layer w0.4: v1(57.404,87.884) R28.2@57.404,88.808
NetR29_1: R29.1 R30.2 R77.1 U9.1 | length 37.5
  Top Layer w0.6: R77.1@57.15,56.41 v1(57.15,57.334) R29.1@57.15,58.42
  Signal Layer 1 w0.3: v1(57.15,57.334) 59.366,57.334 60.96,58.928 v1(60.96,87.884)
  Bottom Layer w0.3: U9.1@59.532,88.833 60.681,88.833 R30.2@60.706,88.808
  Bottom Layer w0.4: v1(60.96,87.884) R30.2@60.96,88.808
NetR32_1: R32.1 R33.2 U11.2 | length 3.3
  Bottom Layer w0.4: U11.2@6.791,24.48 6.791,25.841 6.858,25.908
  Bottom Layer w0.6: R33.2@6.188,25.908 6.858,25.908 R32.1@8.036,25.908
NetR34_1: R34.1 R35.2 U11.1 | length 3.3
  Bottom Layer w0.4: U11.1@6.791,23.78 6.807,23.764 6.807,22.352
  Bottom Layer w0.6: R35.2@6.188,22.352 6.807,22.352 R34.1@8.036,22.352
NetR37_1: R37.1 U10.13 | length 2.7
  Top Layer w0.2: U10.13@22.459,39.225 22.459,41.531 R37.1@22.733,41.805
NetR59_1: R59.1 U13.7 | length 3
  Top Layer w0.22: U13.7@88.63,70.388 88.63,70.758 90.078,72.206 R59.1@90.078,72.806
NetR60_1: R60.1 U13.9 | length 22.2
  Top Layer w0.22: v2(87.376,72.044) 87.376,71.96 87.83,71.506 U13.9@87.83,70.388
  Top Layer w0.4: v2(86.868,81.788) 87.122,81.534
  Bottom Layer w0.4: v2(86.868,81.788) 90.932,81.788 93.726,78.994 93.726,76.962 92.456,75.692 88.392,75.692 87.376,74.676 v2(87.376,72.044)
NetR62_1: R62.1 R64.2 U14.2 | length 3.1
  Bottom Layer w0.4: U14.2@33.37,86.953 34.703,86.953 R64.2@34.798,87.047
  Bottom Layer w0.6: R62.1@34.798,85.453 R64.2@34.798,87.047
NetR63_1: R63.1 U13.8 | length 2.6
  Top Layer w0.22: U13.8@88.23,70.388 88.23,72.806 R63.1@88.392,72.968
NetR65_1: R65.1 R66.2 U14.1 | length 3.1
  Bottom Layer w0.4: R66.2@31.242,87.047 31.337,86.953 U14.1@32.67,86.953
  Bottom Layer w0.6: R65.1@31.242,85.453 R66.2@31.242,87.047
NetR72_2: R72.2 R73.1 U18.1 | length 47.2
  Signal Layer 1 w0.4: v1(88.646,60.452) 88.646,15.748 v1(90.424,13.97)
NetR73_2: R73.2 U13.6 | length 6.8
  Top Layer w0.22: U13.6@88.63,66.588 89.194,66.588 v1(89.408,66.802)
  Signal Layer 1 w0.4: v1(88.646,62.484) 90.17,64.008 90.17,66.04 v1(89.408,66.802)
  Bottom Layer w0.6: R73.2@88.646,61.814 v1(88.646,62.484)
NetR74_2: R74.2 R75.1 U17.1 | length 46.6
  Signal Layer 1 w0.4: v1(86.36,13.97) 86.614,14.224 v1(86.614,60.452)
NetR75_2: R75.2 U13.5 | length 6.8
  Top Layer w0.2: U13.5@88.23,66.588 88.23,66.288 88.732,65.786 v1(89.408,65.786)
  Signal Layer 1 w0.4: v1(86.614,62.484) 86.614,62.992 v1(89.408,65.786)
  Bottom Layer w0.6: R75.2@86.614,61.814 v1(86.614,62.484)
NetR78_2: R78.2 R79.1 R80.1 U7.1 | length 44
  Top Layer w0.6: R80.1@54.102,56.41 v1(54.102,57.658) R79.1@54.102,58.42
  Signal Layer 1 w0.3: v1(54.102,57.658) 55.88,57.658 56.896,56.642 61.214,56.642 63.246,58.674 v1(63.246,87.884)
  Bottom Layer w0.3: R78.2@63.246,88.808 64.579,88.808 U7.1@64.674,88.713
  Bottom Layer w0.4: v1(63.246,87.884) R78.2@63.246,88.808
PACK+: C21.2 C23.1 D9.2 E1.2 J12.6 Q2.1 Q2.2 Q2.3 Q4.2 R55.2 | length 11.5
  Top Layer w0.4: R55.2@82.648,78.578 84.262,78.578 Q2.3@84.425,78.415 Q2.2@84.425,79.065 Q2.1@84.425,79.715
  Top Layer w0.6: D9.2@80.772,78.57 82.64,78.57 R55.2@82.648,78.578 ; Q2.1@84.425,79.715 84.425,80.795 86.871,83.241 C21.2@87.541,83.241
  Bottom Layer w0.6: Q4.2@80.588,78.674 81.722,78.674 v2(81.788,78.74)
PMID: C5.1 C30.1 L1.1 U1.21 U1.22 | length 3.4
  Top Layer w0.4: v2(18.288,65.532) 19.812,65.532 20.574,64.77 21.336,64.77
  other v2: 18.288,64.77 19.05,64.77 19.812,64.77 17.272,69.596 17.272,70.358 17.272,71.12 17.272,71.882
REGN: C8.1 R6.2 U1.11 | length 9.6
  Top Layer w0.3: U1.11@25.014,65.52 27.166,65.52 27.432,65.786 C8.1@27.594,65.786
  Top Layer w0.4: v1(26.975,60.706) R6.2@27.594,60.706 ; C8.1@27.594,65.786 27.594,65.624 v1(27.94,65.278)
  Signal Layer 1 w0.4: v1(26.975,60.706) 27.686,60.706 28.194,61.214 28.194,65.024 v1(27.94,65.278)
RES: J6.5 U10.14 | length 46.3
  Top Layer w0.2: v1(21.844,42.164) 21.844,39.878 21.959,39.763 U10.14@21.959,39.225
  Signal Layer 1 w0.2: v1(21.844,42.164) 26.67,46.99 37.338,46.99 42.926,52.578 57.15,52.578 58.674,51.054 J6.5@58.674,49.53
RST: C20.1 R34.2 R36.1 S1.3 S1.4 U10.1 | length 82.5
  Top Layer w0.3: C20.1@18.45,30.988 18.45,33.436 19.959,34.945 U10.1@19.959,35.425
  Top Layer w0.6: R36.1@16.602,30.988 17.526,30.988 ; C20.1@18.45,30.988 17.526,30.988 ; 49.308,8.971 S1.4@49.308,4.745 49.308,3.221 49.195,3.221 48.514,2.54 13.462,2.54 10.922,5.08 10.922,8.636 9.906,9.652 v1(9.906,22.352) 17.526,29.972 17.526,30.988
  Bottom Layer w0.6: R34.2@9.236,22.352 v1(9.906,22.352)
RX: J5.13 R18.1 | length 3.7
  Bottom Layer w0.3: J5.13@71.628,93.472 71.628,91.694 72.136,91.186 R18.1@72.136,90.008
RX_MCU: R17.2 U10.4 | length 3.7
  Top Layer w0.2: U10.4@21.459,35.425 21.459,33.913 22.86,32.512 R17.2@22.86,32.35
SCL: R41.1 R42.2 R65.2 U1.5 U2.8 | length 109.9
  Top Layer w0.2: U2.8@17.922,49.222 18.742,49.222 20.666,51.146 R41.1@20.666,51.308 ; U1.5@23.864,62.87 23.864,61.988 24.13,61.722 v1(24.13,61.468)
  Signal Layer 1 w0.2: v1(22.098,15.494) 20.32,15.494 11.938,23.876 11.938,39.37 14.732,42.164 17.526,42.164 20.793,45.431 v1(20.793,51.387) 21.59,52.184 21.59,57.658 24.13,60.198 v1(24.13,61.468) 22.86,62.738 17.78,62.738 14.351,66.167 14.351,77.978 20.719,84.346 v1(31.75,84.346)
  Bottom Layer w0.4: R42.2@22.098,12.792 v1(22.098,15.494) ; R65.2@31.242,84.253 31.658,84.253 v1(31.75,84.346)
SCL1: E3.2 J12.1 J15.2 R74.1 | length 105.6
  Signal Layer 1 w0.4: J15.2@87.376,5.954 89.012,4.318 92.71,4.318 100.076,11.684 100.076,35.052 109.474,44.45 109.474,59.436 105.918,62.992 105.918,78.232 97.917,86.233 J12.1@97.917,92.202
SCL_EXT: J10.1 R14.2 R43.2 | length 5.5
  Bottom Layer w0.6: J10.1@16.764,10.16 17.18,9.744 R43.2@22.098,9.744
SCL_MCU: J10.3 U10.10 | length 37.3
  Top Layer w0.2: U10.10@23.109,37.575 24.367,37.575 v1(24.384,37.592)
  Signal Layer 1 w0.2: J10.3@16.764,15.24 18.542,13.462 26.416,13.462 27.178,14.224 27.178,15.24 24.384,18.034 v1(24.384,37.592)
SDA: R38.1 R39.2 R62.2 U1.4 U2.7 | length 122.3
  Top Layer w0.2: U2.7@17.922,48.822 19.612,48.822 21.59,50.8 21.59,52.273 21.031,52.832 R38.1@20.666,52.832 ; U1.4@23.364,62.87 23.364,61.218 v1(23.368,61.214)
  Signal Layer 1 w0.2: v1(26.162,14.732) 19.558,14.732 10.922,23.368 10.922,39.624 14.224,42.926 17.272,42.926 20.066,45.72 20.066,52.324 20.653,52.911 v1(20.793,52.911) 20.828,52.946 20.828,57.912 23.368,60.452 v1(23.368,61.214) 22.352,62.23 17.653,62.23 13.97,65.913 13.97,78.232 21.082,85.344 33.292,85.344 v1(34.29,84.346)
  Bottom Layer w0.4: R39.2@26.162,12.792 v1(26.162,14.732) ; v1(34.29,84.346) 34.382,84.253 R62.2@34.798,84.253
SDA1: E2.2 J12.2 J15.3 R72.1 | length 99.7
  Signal Layer 1 w0.4: J15.3@89.916,5.954 99.06,15.098 99.06,35.56 108.458,44.958 108.458,58.928 104.902,62.484 104.902,77.47 94.412,87.96 J12.2@94.412,92.202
